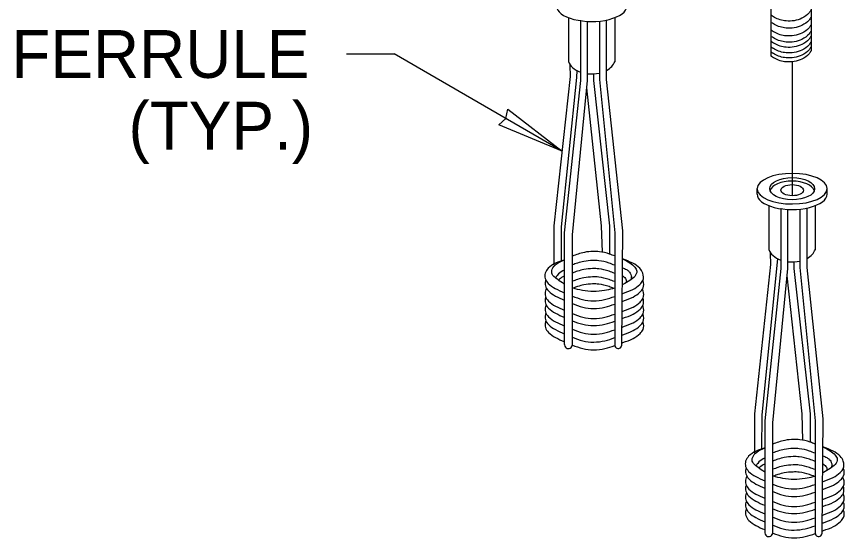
# Model space of a CAD drawing. Extents: x 99862 to 103151, y 103000 to 105076.
# Drawn here: x 101679.6 to 101956.8, y 104042.3 to 104216.9 of the extents above; entities that cross this region are included whole.
import ezdxf

# ---------------------------------------------------------------- set-up
doc = ezdxf.new("R2010")
doc.units = 0
for name, color, linetype in [('Level 15', 7, 'Continuous'), ('Level 20', 7, 'Continuous'), ('Level 3', 7, 'Continuous')]:
    doc.layers.add(name, color=color, linetype=linetype)

msp = doc.modelspace()

# ---------------------------------------------------------------- linework, layer by layer
at = {"layer": 'Level 15'}
for p, q in [((101790.06555632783, 104204.41711661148), (101806.06555632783, 104204.41711661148)), ((101862.35720759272, 104171.91711661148), (101806.06555632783, 104204.41711661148)), ((101939.3320700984, 104201.7576248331), (101939.3320700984, 104156.96335447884))]:
    msp.add_line(p, q, dxfattribs=at)
msp.add_lwpolyline([(101862.35720759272, 104171.91711661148), (101841.09421364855, 104180.74653077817), (101843.50123647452, 104182.80361660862), (101844.0783476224, 104185.91720243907)], close=True, dxfattribs=at)
at = {"layer": 'Level 3'}
for p, q in [((101864.38049014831, 104216.55257911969), (101864.38049014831, 104201.93842615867)), ((101868.52230775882, 104215.54292274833), (101868.42704918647, 104215.5381377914)), ((101879.89229168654, 104216.55257911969), (101879.89229168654, 104201.84428994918)), ((101927.60886730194, 104157.45510461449), (101927.60886730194, 104159.38237300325)), ((101951.05718403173, 104157.45510461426), (101951.05718403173, 104159.36677676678)), ((101931.4985896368, 104153.61826753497), (101931.4985896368, 104139.00411457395)), ((101947.01039117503, 104153.61826753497), (101947.01039117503, 104138.90997836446)), ((101935.64040724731, 104152.60861116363), (101935.54514867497, 104152.60382620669)), ((101863.0316330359, 104135.4251477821), (101863.0206709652, 104135.41957058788)), ((101930.1497325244, 104072.49083619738), (101930.13877045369, 104072.48525900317))]:
    msp.add_line(p, q, dxfattribs=at)
for points in [[(101932.15468359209, 104219.67888738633), (101932.15468359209, 104203.78595245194)], [(101945.64320564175, 104221.36962504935), (101945.64320564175, 104205.47669011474)], [(101868.42704918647, 104215.5381377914), (101868.42704918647, 104195.58743739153), (101863.03163303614, 104144.52716940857), (101863.03163303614, 104107.40945213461)], [(101865.75388959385, 104107.23119532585), (101865.72934115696, 104143.85087923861), (101870.78753995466, 104195.58743739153), (101870.78753995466, 104215.32700900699)], [(101874.83409896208, 104215.42932648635), (101874.83409896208, 104195.92558851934), (101879.89229168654, 104144.52716940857), (101879.89229168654, 104106.91004455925)], [(101882.24910177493, 104107.25873987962), (101882.58999971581, 104145.20346565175), (101877.19458969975, 104195.92558851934), (101877.19458969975, 104215.79068036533)], [(101859.65950263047, 104133.73449870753), (101859.65950263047, 104146.89420334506), (101865.05491255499, 104196.94002987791), (101865.00907209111, 104200.72630621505)], [(101867.25749548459, 104198.86088914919), (101867.07819210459, 104196.60187875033), (101862.01999941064, 104146.5560582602), (101861.96715947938, 104134.92350953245)], [(101872.81844289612, 104197.74495573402), (101872.81081941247, 104195.58743739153), (101878.2062294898, 104146.89420334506), (101878.2062294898, 104137.42607382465)], [(101875.82274822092, 104138.07158341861), (101875.50852136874, 104146.89420334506), (101870.54040225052, 104193.05964939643)], [(101935.54514867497, 104152.60382620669), (101935.54514867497, 104132.65312580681), (101930.14973252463, 104081.59285782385), (101930.14973252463, 104044.4751405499)], [(101932.87198908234, 104044.29688374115), (101932.84744064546, 104080.9165676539), (101937.90563944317, 104132.65312580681), (101937.90563944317, 104152.39269742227)], [(101941.95219845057, 104152.49501490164), (101941.95219845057, 104132.99127693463), (101947.01039117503, 104081.59285782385), (101947.01039117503, 104043.97573297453)], [(101949.36720126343, 104044.3244282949), (101949.7080992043, 104082.26915406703), (101944.31268918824, 104132.99127693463), (101944.31268918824, 104152.85636878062)], [(101926.77760211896, 104070.80018712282), (101926.77760211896, 104083.95989176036), (101932.17301204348, 104134.00571829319), (101932.1271715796, 104137.79199463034)], [(101934.37559497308, 104135.92657756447), (101934.19629159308, 104133.66756716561), (101929.13809889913, 104083.62174667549), (101929.08525896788, 104071.98919794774)], [(101939.93654238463, 104134.8106441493), (101939.92891890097, 104132.65312580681), (101945.3243289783, 104083.95989176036), (101945.3243289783, 104074.49176223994)], [(101942.94084770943, 104075.1372718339), (101942.62662085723, 104083.95989176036), (101937.65850173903, 104130.12533781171)]]:
    msp.add_lwpolyline(points, dxfattribs=at)
for centre, major_axis, ratio, start_param, end_param in [((101872.21397060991, 104220.40585306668), (11.724880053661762, 0.03934682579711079), 0.4360721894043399, 3.1231513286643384, 6.281721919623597), ((101872.15239258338, 104203.08907726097), (-7.957212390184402, 9.744774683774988e-16), 0.6739724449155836, 0.21623717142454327, 1.0835754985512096), ((101872.15239258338, 104203.08907726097), (-7.957212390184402, 9.744774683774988e-16), 0.6739724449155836, 2.257076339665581, 2.907347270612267), ((101872.15239258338, 104203.08907726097), (-7.957212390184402, 9.744774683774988e-16), 0.6739724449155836, 1.398419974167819, 1.9145418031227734), ((101939.3320700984, 104159.32742994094), (11.724880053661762, 0.03934682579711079), 0.4360721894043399, 3.1571072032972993, 9.406336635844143), ((101939.3320700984, 104158.14588949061), (-7.496269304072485, 0.039346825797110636), 0.4971757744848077, 3.303382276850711, 6.126614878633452), ((101939.3320700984, 104157.47154148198), (11.724880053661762, 0.03934682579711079), 0.4360721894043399, 3.1231513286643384, 6.281721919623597), ((101939.27049207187, 104140.15476567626), (-7.957212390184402, 9.744774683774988e-16), 0.6739724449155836, 0.21623717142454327, 1.0835754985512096), ((101939.27049207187, 104140.15476567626), (-7.957212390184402, 9.744774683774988e-16), 0.6739724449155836, 2.257076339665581, 2.907347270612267), ((101939.27049207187, 104140.15476567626), (-7.957212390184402, 9.744774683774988e-16), 0.6739724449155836, 1.398419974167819, 1.9145418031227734), ((101864.39222581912, 104107.30913547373), (0.056452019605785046, -1.49597852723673), 0.9103568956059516, 4.610981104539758, 7.7675494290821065), ((101881.0712043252, 104107.08065660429), (2.3283100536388e-10, -1.2419444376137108), 0.9583333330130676, 4.850199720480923, 7.9978683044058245), ((101931.51032530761, 104044.37482388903), (0.056452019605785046, -1.49597852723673), 0.9103568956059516, 4.610981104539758, 7.7675494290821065), ((101948.18930381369, 104044.14634501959), (2.3283100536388e-10, -1.2419444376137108), 0.9583333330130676, 4.850199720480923, 7.9978683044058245)]:
    msp.add_ellipse(centre, major_axis=major_axis, ratio=ratio, start_param=start_param, end_param=end_param, dxfattribs=at)
for centre, major_axis in [((101939.3320700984, 104159.32742994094), (-7.496269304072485, 0.039346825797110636)), ((101939.3320700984, 104158.82688122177), (-3.7481346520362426, 0.019673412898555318))]:
    msp.add_ellipse(centre, major_axis=major_axis, ratio=0.4971757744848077, dxfattribs=at)
for points in [[(101945.64320564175, 104219.16897752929), (101944.96878314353, 104218.15453620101), (101942.6082864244, 104216.3772751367), (101937.32613901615, 104215.47404281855), (101933.3744976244, 104216.68776124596), (101932.15468359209, 104217.4782398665)], [(101945.64320564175, 104216.78858402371), (101944.96878314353, 104215.77414269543), (101942.6082864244, 104213.99688163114), (101937.32613901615, 104213.09364931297), (101933.3744976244, 104214.30736774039), (101932.15468359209, 104215.09784636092)], [(101945.64320564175, 104214.18238243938), (101944.96878314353, 104213.1679411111), (101942.6082864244, 104211.3906800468), (101937.32613901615, 104210.48744772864), (101933.3744976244, 104211.70116615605), (101932.15468359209, 104212.49164477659)], [(101945.64320564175, 104212.1124750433), (101944.96878314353, 104211.09803371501), (101942.6082864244, 104209.32077265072), (101937.32613901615, 104208.41754033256), (101933.3744976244, 104209.63125875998), (101932.15468359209, 104210.4217373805)], [(101945.64320564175, 104210.3812797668), (101944.96878314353, 104209.36683843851), (101942.6082864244, 104207.58957737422), (101937.32613901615, 104206.68634505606), (101933.3744976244, 104207.90006348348), (101932.15468359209, 104208.69054210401)], [(101945.64320564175, 104208.52002026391), (101944.96878314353, 104207.50557893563), (101942.6082864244, 104205.72831787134), (101937.32613901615, 104204.82508555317), (101933.3744976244, 104206.03880398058), (101932.15468359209, 104206.82928260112)], [(101945.64320564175, 104206.82928266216), (101944.96878314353, 104205.81484133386), (101942.6082864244, 104204.03758026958), (101937.32613901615, 104203.13434795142), (101933.3744976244, 104204.34806637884), (101932.15468359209, 104205.13854499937)], [(101945.64320564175, 104205.47669011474), (101944.96878314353, 104204.46224878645), (101942.6082864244, 104202.68498772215), (101937.32613901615, 104201.781755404), (101933.3744976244, 104202.99547383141), (101932.15468359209, 104203.78595245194)], [(101879.89229168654, 104136.79839686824), (101878.2062294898, 104137.42607382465), (101874.76269110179, 104138.24217158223), (101872.69248968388, 104138.30803227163), (101869.75727867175, 104138.01636350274), (101867.64973659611, 104137.45184330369), (101865.7293411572, 104136.77035881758)], [(101863.03948830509, 104135.47602260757), (101857.63622305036, 104132.6920121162), (101856.6245832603, 104131.00127451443), (101856.6245832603, 104129.31053682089), (101857.63622305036, 104127.61979921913), (101859.99671989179, 104125.9290615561), (101863.03163303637, 104124.50653457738)], [(101863.03163303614, 104127.39617939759), (101862.38088140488, 104127.77973056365), (101860.3339311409, 104129.31053682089), (101858.98508013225, 104130.66312326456), (101858.98508013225, 104132.35386086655), (101860.3339311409, 104134.04459852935), (101863.03948830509, 104135.47602260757)], [(101879.8922916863, 104133.71113245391), (101878.01735577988, 104134.40912216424), (101874.57381739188, 104135.22521992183), (101872.50361597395, 104135.29108061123), (101869.56840496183, 104134.99941184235), (101867.46086288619, 104134.4348916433), (101865.73606358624, 104133.82281772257)], [(101882.40101765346, 104124.16821825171), (101882.58999971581, 104124.23832395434), (101885.96213021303, 104125.59091647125), (101888.3226209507, 104127.281654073), (101889.33426074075, 104128.6342405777), (101889.33426074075, 104131.00127451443), (101888.3226209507, 104132.6920121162), (101885.96213021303, 104134.38274971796), (101882.53425250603, 104135.81473472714), (101882.50574722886, 104135.82547557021)], [(101882.58999971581, 104135.73533616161), (101884.94728233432, 104134.53515560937), (101886.63655872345, 104133.0301572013), (101887.31098116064, 104131.67757069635), (101886.63655872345, 104129.9868330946), (101884.95049045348, 104128.6342405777), (101882.6659738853, 104127.29047972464), (101882.42798633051, 104127.17005230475)], [(101863.03163303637, 104132.10782031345), (101862.52581622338, 104131.84664326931), (101860.67114232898, 104130.32497817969), (101860.11979826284, 104129.48453765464)], [(101879.89229168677, 104130.98261816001), (101878.01735577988, 104131.68060786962), (101874.57381739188, 104132.4967056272), (101872.50361597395, 104132.56256631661), (101869.56840496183, 104132.27089754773), (101867.46086288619, 104131.70637734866), (101865.7378922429, 104131.094952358)], [(101882.46339345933, 104132.86041235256), (101883.82523577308, 104132.23870173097), (101884.65561356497, 104131.64669392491), (101885.12604706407, 104130.99749569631), (101885.45535051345, 104130.16953273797), (101885.45535051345, 104129.4638824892), (101885.29725580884, 104128.85154384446)], [(101856.81548418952, 104128.81833571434), (101856.70725545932, 104128.47559752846), (101856.70725545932, 104126.78485983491), (101857.71889524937, 104125.09412223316), (101860.0793920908, 104123.40338457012), (101863.03163303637, 104122.01699721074)], [(101863.03163303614, 104130.06602816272), (101862.52581622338, 104129.81775750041), (101861.0353142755, 104128.7501665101)], [(101879.89229168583, 104128.21646918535), (101878.01735577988, 104128.9144588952), (101874.57381739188, 104129.73055665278), (101872.50361597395, 104129.7964173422), (101869.56840496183, 104129.50474857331), (101867.46086288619, 104128.94022837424), (101865.73974612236, 104128.32946126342)], [(101882.37797569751, 104121.60346028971), (101882.67267191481, 104121.71264696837), (101886.04480241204, 104123.06523948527), (101888.40529314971, 104124.75597708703), (101889.41693293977, 104126.10856359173), (101889.41693293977, 104128.47559752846), (101889.34669226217, 104128.66183531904)], [(101882.49161946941, 104130.10367204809), (101882.96205296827, 104129.87786396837), (101883.47952981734, 104129.31334376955), (101883.79001592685, 104128.654736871), (101883.79001592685, 104128.07139933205), (101883.7900159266, 104127.91973151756)], [(101857.02731488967, 104125.98233773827), (101856.70725545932, 104125.09412223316), (101856.70725545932, 104123.4033845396), (101857.71889524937, 104121.71264693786), (101860.0793920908, 104120.02190927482), (101863.0316330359, 104118.6355219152)], [(101879.89229168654, 104126.06567389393), (101879.16594865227, 104125.82272720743), (101876.5201611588, 104125.25276528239), (101872.81081941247, 104124.91462019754), (101869.1014716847, 104125.25276528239), (101865.84327195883, 104126.12380464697), (101865.74119972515, 104126.16107561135)], [(101879.58628606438, 104125.95940225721), (101878.01735577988, 104126.54347405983), (101874.57381739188, 104127.3595718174), (101872.50361597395, 104127.4254325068), (101869.56840496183, 104127.13376373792), (101867.46086288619, 104126.56924353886), (101866.02406733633, 104126.05937257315)], [(101882.3474952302, 104118.21073530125), (101882.67267191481, 104118.33117167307), (101886.04480241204, 104119.68376418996), (101888.40529314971, 104121.37450179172), (101889.41693293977, 104122.72708829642), (101889.41693293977, 104125.09412223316), (101889.18032266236, 104125.66794306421)], [(101856.81598792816, 104123.07135381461), (101856.70725545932, 104122.72709440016), (101856.70725545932, 104121.03635670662), (101857.71889524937, 104119.34561910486), (101860.0793920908, 104117.65488144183), (101863.03163303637, 104116.26849408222)], [(101865.74306578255, 104123.37741893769), (101869.1014716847, 104122.20944123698), (101876.5201611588, 104122.20944123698), (101879.89229168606, 104123.27247440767)], [(101882.32615899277, 104115.83583770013), (101882.67267191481, 104115.96414384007), (101886.04480241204, 104117.31673635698), (101888.40529314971, 104119.00747395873), (101889.41693293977, 104120.36006046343), (101889.41693417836, 104122.72709099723)], [(101856.91089364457, 104120.4650531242), (101856.70725545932, 104119.85253362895), (101856.70725545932, 104118.16179593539), (101857.71889524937, 104116.47105833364), (101860.0793920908, 104114.7803206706), (101863.0316330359, 104113.39393331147)], [(101865.74473765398, 104120.88343490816), (101869.1841438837, 104119.68376425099), (101876.60283335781, 104119.68376425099), (101879.8922916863, 104120.71858255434)], [(101882.3002479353, 104112.9517253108), (101882.67267191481, 104113.08958306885), (101886.04480241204, 104114.44217558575), (101888.40529314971, 104116.13291318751), (101889.41693293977, 104117.48549969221), (101889.41693293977, 104119.85253362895), (101889.30684950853, 104120.13834452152)], [(101856.86386667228, 104117.70244707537), (101856.70725545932, 104117.21810603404), (101856.70725545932, 104115.5273683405), (101857.71889524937, 104113.83663073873), (101860.0793920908, 104112.1458930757), (101863.03163303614, 104110.7595057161)], [(101865.74700506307, 104117.5010679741), (101869.1841438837, 104116.30228895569), (101876.60283335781, 104116.30228895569), (101879.8922916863, 104117.3371072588)], [(101882.27650146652, 104110.30854940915), (101882.67267191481, 104110.45515547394), (101886.04480241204, 104111.80774799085), (101888.40529314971, 104113.4984855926), (101889.41693293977, 104114.8510720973), (101889.41693293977, 104117.21810603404), (101889.36077501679, 104117.3680976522)], [(101856.8634101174, 104115.0667280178), (101856.70725545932, 104114.58367843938), (101856.70725545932, 104112.89294074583), (101857.71889524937, 104111.20220314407), (101860.0793920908, 104109.51146548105), (101863.0316330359, 104108.12507812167)], [(101865.74859224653, 104115.1334160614), (101869.1841438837, 104113.93526112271), (101876.60283335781, 104113.93526112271), (101879.89229168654, 104114.97007942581)], [(101882.2527550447, 104107.66537869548), (101882.67267191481, 104107.82072787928), (101886.04480241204, 104109.17332039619), (101888.40529314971, 104110.86405799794), (101889.41693293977, 104112.21664450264), (101889.41693293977, 104114.58367843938), (101889.36077501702, 104114.73367005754)], [(101865.7505197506, 104112.25809747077), (101869.1841438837, 104111.06070035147), (101876.60283335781, 104111.06070035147), (101879.8922916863, 104112.09551865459)], [(101865.75228623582, 104109.62297543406), (101869.1841438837, 104108.42627275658), (101876.60283335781, 104108.42627275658), (101879.89229168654, 104109.46109105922)], [(101865.7275301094, 104106.99829975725), (101869.1841438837, 104105.79184516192), (101876.60283335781, 104105.79184516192), (101879.90528505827, 104106.83109165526)], [(101947.01039117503, 104073.86408528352), (101945.3243289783, 104074.49176223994), (101941.8807905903, 104075.30785999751), (101939.81058917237, 104075.37372068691), (101936.87537816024, 104075.08205191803), (101934.7678360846, 104074.51753171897), (101932.8474406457, 104073.83604723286)], [(101949.51911714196, 104061.233906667), (101949.7080992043, 104061.30401236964), (101953.08022970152, 104062.65660488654), (101955.4407204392, 104064.3473424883), (101956.45236022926, 104065.699928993), (101956.45236022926, 104068.06696292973), (101955.4407204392, 104069.75770053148), (101953.08022970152, 104071.44843813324), (101949.65235199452, 104072.88042314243), (101949.62384671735, 104072.89116398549)], [(101949.7080992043, 104072.80102457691), (101952.06538182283, 104071.60084402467), (101953.75465821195, 104070.09584561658), (101954.42908064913, 104068.74325911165), (101953.75465821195, 104067.05252150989), (101952.06858994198, 104065.699928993), (101949.7840733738, 104064.35616813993), (101949.546085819, 104064.23574072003)], [(101930.1575877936, 104072.54171102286), (101924.75432253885, 104069.75770053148), (101923.7426827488, 104068.06696292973), (101923.7426827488, 104066.37622523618), (101924.75432253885, 104064.68548763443), (101927.11481938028, 104062.99474997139), (101930.14973252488, 104061.57222299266)], [(101930.14973252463, 104064.46186781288), (101929.49898089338, 104064.84541897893), (101927.4520306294, 104066.37622523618), (101926.10317962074, 104067.72881167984), (101926.10317962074, 104069.41954928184), (101927.4520306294, 104071.11028694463), (101930.1575877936, 104072.54171102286)], [(101947.0103911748, 104070.77682086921), (101945.13545526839, 104071.47481057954), (101941.69191688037, 104072.29090833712), (101939.62171546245, 104072.35676902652), (101936.68650445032, 104072.06510025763), (101934.57896237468, 104071.50058005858), (101932.85416307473, 104070.88850613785)], [(101949.58149294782, 104069.92610076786), (101950.94333526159, 104069.30439014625), (101951.77371305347, 104068.71238234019), (101952.24414655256, 104068.0631841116), (101952.57345000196, 104067.23522115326), (101952.57345000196, 104066.5295709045), (101952.41535529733, 104065.91723225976)], [(101930.14973252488, 104069.17350872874), (101929.64391571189, 104068.9123316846), (101927.78924181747, 104067.39066659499), (101927.23789775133, 104066.55022606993)], [(101930.14973252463, 104067.131716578), (101929.64391571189, 104066.88344591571), (101928.153413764, 104065.8158549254)], [(101947.01039117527, 104068.0483065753), (101945.13545526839, 104068.74629628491), (101941.69191688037, 104069.5623940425), (101939.62171546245, 104069.6282547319), (101936.68650445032, 104069.33658596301), (101934.57896237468, 104068.77206576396), (101932.85599173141, 104068.1606407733)], [(101949.6097189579, 104067.16936046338), (101950.08015245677, 104066.94355238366), (101950.59762930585, 104066.37903218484), (101950.90811541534, 104065.7204252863), (101950.90811541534, 104065.13708774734), (101950.90811541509, 104064.98541993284)], [(101923.93358367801, 104065.88402412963), (101923.82535494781, 104065.54128594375), (101923.82535494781, 104063.85054825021), (101924.83699473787, 104062.15981064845), (101927.1974915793, 104060.46907298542), (101930.14973252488, 104059.08268562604)], [(101947.01039117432, 104065.28215760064), (101945.13545526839, 104065.9801473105), (101941.69191688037, 104066.79624506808), (101939.62171546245, 104066.86210575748), (101936.68650445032, 104066.5704369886), (101934.57896237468, 104066.00591678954), (101932.85784561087, 104065.3951496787)], [(101946.70438555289, 104063.0250906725), (101945.13545526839, 104063.60916247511), (101941.69191688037, 104064.42526023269), (101939.62171546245, 104064.49112092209), (101936.68650445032, 104064.1994521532), (101934.57896237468, 104063.63493195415), (101933.14216682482, 104063.12506098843)], [(101949.49607518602, 104058.66914870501), (101949.79077140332, 104058.77833538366), (101953.16290190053, 104060.13092790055), (101955.5233926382, 104061.82166550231), (101956.53503242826, 104063.17425200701), (101956.53503242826, 104065.54128594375), (101956.46479175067, 104065.72752373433)], [(101924.14541437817, 104063.04802615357), (101923.82535494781, 104062.15981064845), (101923.82535494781, 104060.46907295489), (101924.83699473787, 104058.77833535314), (101927.1974915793, 104057.0875976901), (101930.1497325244, 104055.70121033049)], [(101947.01039117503, 104063.13136230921), (101946.28404814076, 104062.88841562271), (101943.6382606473, 104062.31845369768), (101939.92891890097, 104061.98030861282), (101936.21957117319, 104062.31845369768), (101932.96137144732, 104063.18949306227), (101932.85929921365, 104063.22676402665)], [(101949.4655947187, 104055.27642371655), (101949.79077140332, 104055.39686008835), (101953.16290190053, 104056.74945260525), (101955.5233926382, 104058.44019020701), (101956.53503242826, 104059.7927767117), (101956.53503242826, 104062.15981064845), (101956.29842215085, 104062.73363147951)], [(101923.93408741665, 104060.1370422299), (101923.82535494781, 104059.79278281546), (101923.82535494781, 104058.10204512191), (101924.83699473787, 104056.41130752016), (101927.1974915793, 104054.72056985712), (101930.14973252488, 104053.3341824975)], [(101932.86116527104, 104060.44310735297), (101936.21957117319, 104059.27512965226), (101943.6382606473, 104059.27512965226), (101947.01039117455, 104060.33816282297)], [(101949.44425848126, 104052.90152611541), (101949.79077140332, 104053.02983225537), (101953.16290190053, 104054.38242477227), (101955.5233926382, 104056.07316237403), (101956.53503242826, 104057.42574887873), (101956.53503366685, 104059.79277941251)], [(101924.02899313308, 104057.53074153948), (101923.82535494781, 104056.91822204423), (101923.82535494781, 104055.22748435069), (101924.83699473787, 104053.53674674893), (101927.1974915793, 104051.8460090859), (101930.1497325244, 104050.45962172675)], [(101932.86283714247, 104057.94912332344), (101936.3022433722, 104056.74945266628), (101943.7209328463, 104056.74945266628), (101947.0103911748, 104057.78427096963)], [(101949.4183474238, 104050.01741372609), (101949.79077140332, 104050.15527148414), (101953.16290190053, 104051.50786400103), (101955.5233926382, 104053.1986016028), (101956.53503242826, 104054.55118810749), (101956.53503242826, 104056.91822204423), (101956.42494899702, 104057.20403293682)], [(101923.98196616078, 104054.76813549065), (101923.82535494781, 104054.28379444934), (101923.82535494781, 104052.59305675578), (101924.83699473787, 104050.90231915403), (101927.1974915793, 104049.21158149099), (101930.14973252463, 104047.82519413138)], [(101932.86510455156, 104054.56675638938), (101936.3022433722, 104053.36797737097), (101943.7209328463, 104053.36797737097), (101947.0103911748, 104054.40279567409)], [(101949.39460095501, 104047.37423782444), (101949.79077140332, 104047.52084388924), (101953.16290190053, 104048.87343640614), (101955.5233926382, 104050.5641740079), (101956.53503242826, 104051.9167605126), (101956.53503242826, 104054.28379444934), (101956.47887450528, 104054.43378606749)], [(101923.98150960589, 104052.1324164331), (101923.82535494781, 104051.64936685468), (101923.82535494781, 104049.95862916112), (101924.83699473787, 104048.26789155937), (101927.1974915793, 104046.57715389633), (101930.1497325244, 104045.19076653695)], [(101932.86669173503, 104052.19910447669), (101936.3022433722, 104051.00094953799), (101943.7209328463, 104051.00094953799), (101947.01039117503, 104052.03576784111)], [(101949.3708545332, 104044.73106711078), (101949.79077140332, 104044.88641629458), (101953.16290190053, 104046.23900881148), (101955.5233926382, 104047.92974641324), (101956.53503242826, 104049.28233291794), (101956.53503242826, 104051.64936685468), (101956.47887450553, 104051.79935847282)], [(101932.86861923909, 104049.32378588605), (101936.3022433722, 104048.12638876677), (101943.7209328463, 104048.12638876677), (101947.0103911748, 104049.16120706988)], [(101932.87038572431, 104046.68866384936), (101936.3022433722, 104045.49196117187), (101943.7209328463, 104045.49196117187), (101947.01039117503, 104046.5267794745)], [(101932.8456295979, 104044.06398817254), (101936.3022433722, 104042.8575335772), (101943.7209328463, 104042.8575335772), (101947.02338454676, 104043.89678007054)]]:
    msp.add_spline(points, degree=3, dxfattribs=at)

# ---------------------------------------------------------------- texts
at = {"layer": 'Level 20'}
for s, p in [('FERRULE', (101677.84894579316, 104196.41948323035)), ('(TYP.)', (101717.09699757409, 104172.41948123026))]:
    msp.add_text(s, height=16.000002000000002, dxfattribs=at).set_placement(p)

doc.saveas('drawing.dxf')
